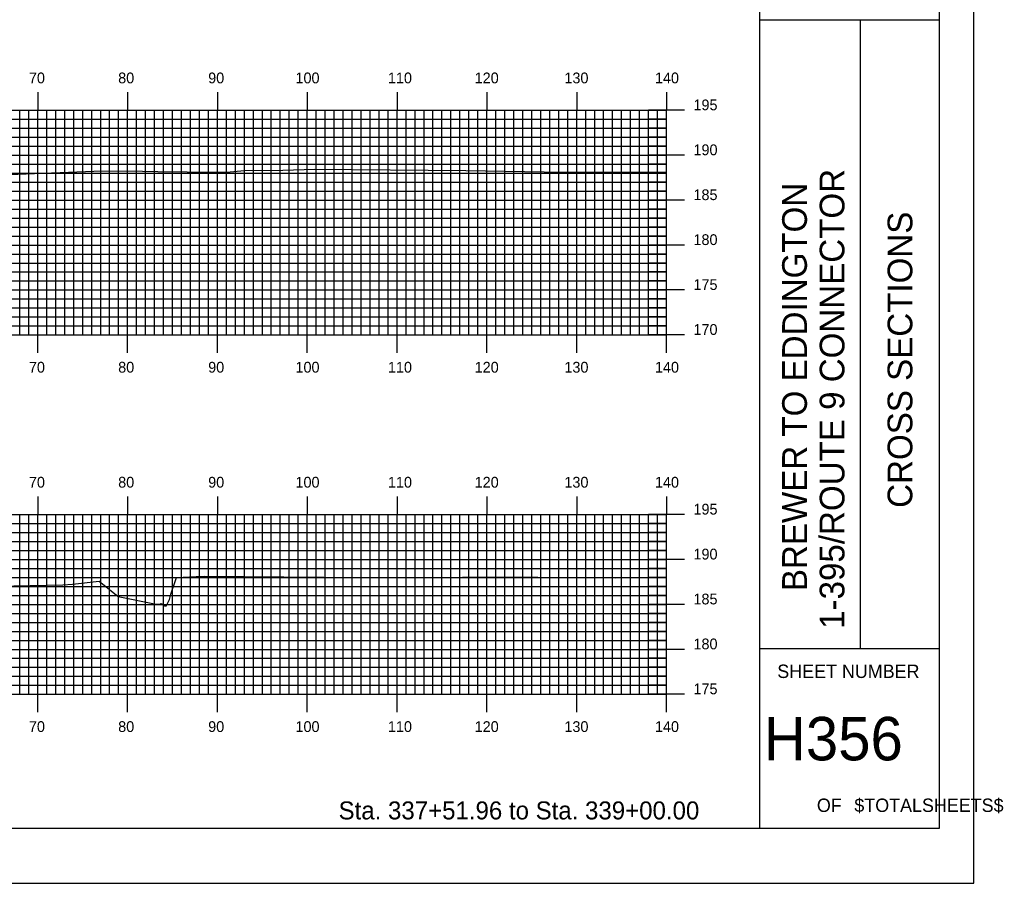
# Model space of a CAD drawing. Extents: x 1823966 to 1824309, y 442591 to 442811.
# Drawn here: x 1824199.8 to 1824309.3, y 442590.5 to 442686.7 of the extents above; entities that cross this region are included whole.
import ezdxf

# ---------------------------------------------------------------- set-up
doc = ezdxf.new("R2010")
doc.units = 0
for name, color, linetype in [('BORDER', 7, 'Continuous'), ('H_V ANNOTATION', 7, 'Continuous'), ('MAJOR', 7, 'Continuous'), ('MINOR', 7, 'Continuous'), ('PLOT BOUNDARY', 7, 'Continuous'), ('S_Roadway_Centerline', 7, 'Continuous')]:
    doc.layers.add(name, color=color, linetype=linetype)

msp = doc.modelspace()

# ---------------------------------------------------------------- linework, layer by layer
at = {"layer": 'BORDER'}
for p, q in [((1824282.22, 442596.67), (1824282.22, 442806.67)), ((1824282.22, 442686.67), (1824302.22, 442686.67)), ((1824293.4, 442616.67), (1824293.4, 442686.67)), ((1824282.22, 442616.67), (1824302.22, 442616.67))]:
    msp.add_line(p, q, dxfattribs=at)
msp.add_lwpolyline([(1823982.22, 442596.67), (1824302.22, 442596.67), (1824302.22, 442806.67), (1823982.22, 442806.67)], close=True, dxfattribs=at)
at = {"layer": 'MAJOR'}
for p, q in [((1824201.82, 442678.59), (1824201.82, 442676.59)), ((1824211.82, 442678.59), (1824211.82, 442676.59)), ((1824221.82, 442678.59), (1824221.82, 442676.59)), ((1824231.82, 442678.59), (1824231.82, 442676.59)), ((1824241.82, 442678.59), (1824241.82, 442676.59)), ((1824251.82, 442678.59), (1824251.82, 442676.59)), ((1824261.82, 442678.59), (1824261.82, 442676.59)), ((1824271.82, 442678.59), (1824271.82, 442676.59)), ((1823991.82, 442676.59), (1824271.82, 442676.59)), ((1823991.82, 442676.59), (1824271.82, 442676.59)), ((1824201.82, 442651.59), (1824201.82, 442676.59)), ((1824211.82, 442651.59), (1824211.82, 442676.59)), ((1824221.82, 442651.59), (1824221.82, 442676.59)), ((1824231.82, 442651.59), (1824231.82, 442676.59)), ((1824241.82, 442651.59), (1824241.82, 442676.59)), ((1824251.82, 442651.59), (1824251.82, 442676.59)), ((1824261.82, 442651.59), (1824261.82, 442676.59)), ((1824273.83, 442676.59), (1824269.82, 442676.59)), ((1824271.82, 442651.59), (1824271.82, 442676.59)), ((1824271.82, 442651.59), (1824271.82, 442676.59)), ((1823991.82, 442671.59), (1824271.82, 442671.59)), ((1824273.83, 442671.59), (1824269.82, 442671.59)), ((1823991.82, 442666.59), (1824271.82, 442666.59)), ((1824273.83, 442666.59), (1824269.82, 442666.59)), ((1823991.82, 442661.59), (1824271.82, 442661.59)), ((1824273.83, 442661.59), (1824269.82, 442661.59)), ((1823991.82, 442656.59), (1824271.82, 442656.59)), ((1824273.83, 442656.59), (1824269.82, 442656.59)), ((1823991.82, 442651.59), (1824271.82, 442651.59)), ((1823991.82, 442651.59), (1824271.82, 442651.59)), ((1824201.82, 442649.58), (1824201.82, 442651.59)), ((1824211.82, 442649.58), (1824211.82, 442651.59)), ((1824221.82, 442649.58), (1824221.82, 442651.59)), ((1824231.82, 442649.58), (1824231.82, 442651.59)), ((1824241.82, 442649.58), (1824241.82, 442651.59)), ((1824251.82, 442649.58), (1824251.82, 442651.59)), ((1824261.82, 442649.58), (1824261.82, 442651.59)), ((1824273.83, 442651.59), (1824269.82, 442651.59)), ((1824271.82, 442649.58), (1824271.82, 442651.59)), ((1824201.82, 442633.59), (1824201.82, 442631.59)), ((1824211.82, 442633.59), (1824211.82, 442631.59)), ((1824221.82, 442633.59), (1824221.82, 442631.59)), ((1824231.82, 442633.59), (1824231.82, 442631.59)), ((1824241.82, 442633.59), (1824241.82, 442631.59)), ((1824251.82, 442633.59), (1824251.82, 442631.59)), ((1824261.82, 442633.59), (1824261.82, 442631.59)), ((1824271.82, 442633.59), (1824271.82, 442631.59)), ((1824131.82, 442631.59), (1824271.82, 442631.59)), ((1824131.82, 442631.59), (1824271.82, 442631.59)), ((1824201.82, 442611.59), (1824201.82, 442631.59)), ((1824211.82, 442611.59), (1824211.82, 442631.59)), ((1824221.82, 442611.59), (1824221.82, 442631.59)), ((1824231.82, 442611.59), (1824231.82, 442631.59)), ((1824241.82, 442611.59), (1824241.82, 442631.59)), ((1824251.82, 442611.59), (1824251.82, 442631.59)), ((1824261.82, 442611.59), (1824261.82, 442631.59)), ((1824273.83, 442631.59), (1824269.82, 442631.59)), ((1824271.82, 442611.59), (1824271.82, 442631.59)), ((1824271.82, 442611.59), (1824271.82, 442631.59)), ((1824131.82, 442626.59), (1824271.82, 442626.59)), ((1824273.83, 442626.59), (1824269.82, 442626.59)), ((1824131.82, 442621.59), (1824271.82, 442621.59)), ((1824273.83, 442621.59), (1824269.82, 442621.59)), ((1824131.82, 442616.59), (1824271.82, 442616.59)), ((1824273.83, 442616.59), (1824269.82, 442616.59)), ((1824131.82, 442611.59), (1824271.82, 442611.59)), ((1824131.82, 442611.59), (1824271.82, 442611.59)), ((1824201.82, 442609.58), (1824201.82, 442611.59)), ((1824211.82, 442609.58), (1824211.82, 442611.59)), ((1824221.82, 442609.58), (1824221.82, 442611.59)), ((1824231.82, 442609.58), (1824231.82, 442611.59)), ((1824241.82, 442609.58), (1824241.82, 442611.59)), ((1824251.82, 442609.58), (1824251.82, 442611.59)), ((1824261.82, 442609.58), (1824261.82, 442611.59)), ((1824273.83, 442611.59), (1824269.82, 442611.59)), ((1824271.82, 442609.58), (1824271.82, 442611.59))]:
    msp.add_line(p, q, dxfattribs=at)
at = {"layer": 'MINOR'}
for p, q in [((1824199.82, 442651.59), (1824199.82, 442676.59)), ((1824200.82, 442651.59), (1824200.82, 442676.59)), ((1824202.82, 442651.59), (1824202.82, 442676.59)), ((1824203.82, 442651.59), (1824203.82, 442676.59)), ((1824204.82, 442651.59), (1824204.82, 442676.59)), ((1824205.82, 442651.59), (1824205.82, 442676.59)), ((1824206.82, 442651.59), (1824206.82, 442676.59)), ((1824207.82, 442651.59), (1824207.82, 442676.59)), ((1824208.82, 442651.59), (1824208.82, 442676.59)), ((1824209.82, 442651.59), (1824209.82, 442676.59)), ((1824210.82, 442651.59), (1824210.82, 442676.59)), ((1824212.82, 442651.59), (1824212.82, 442676.59)), ((1824213.82, 442651.59), (1824213.82, 442676.59)), ((1824214.82, 442651.59), (1824214.82, 442676.59)), ((1824215.82, 442651.59), (1824215.82, 442676.59)), ((1824216.82, 442651.59), (1824216.82, 442676.59)), ((1824217.82, 442651.59), (1824217.82, 442676.59)), ((1824218.82, 442651.59), (1824218.82, 442676.59)), ((1824219.82, 442651.59), (1824219.82, 442676.59)), ((1824220.82, 442651.59), (1824220.82, 442676.59)), ((1824222.82, 442651.59), (1824222.82, 442676.59)), ((1824223.82, 442651.59), (1824223.82, 442676.59)), ((1824224.82, 442651.59), (1824224.82, 442676.59)), ((1824225.82, 442651.59), (1824225.82, 442676.59)), ((1824226.82, 442651.59), (1824226.82, 442676.59)), ((1824227.82, 442651.59), (1824227.82, 442676.59)), ((1824228.82, 442651.59), (1824228.82, 442676.59)), ((1824229.82, 442651.59), (1824229.82, 442676.59)), ((1824230.82, 442651.59), (1824230.82, 442676.59)), ((1824232.82, 442651.59), (1824232.82, 442676.59)), ((1824233.82, 442651.59), (1824233.82, 442676.59)), ((1824234.82, 442651.59), (1824234.82, 442676.59)), ((1824235.82, 442651.59), (1824235.82, 442676.59)), ((1824236.82, 442651.59), (1824236.82, 442676.59)), ((1824237.82, 442651.59), (1824237.82, 442676.59)), ((1824238.82, 442651.59), (1824238.82, 442676.59)), ((1824239.82, 442651.59), (1824239.82, 442676.59)), ((1824240.82, 442651.59), (1824240.82, 442676.59)), ((1824242.82, 442651.59), (1824242.82, 442676.59)), ((1824243.82, 442651.59), (1824243.82, 442676.59)), ((1824244.82, 442651.59), (1824244.82, 442676.59)), ((1824245.82, 442651.59), (1824245.82, 442676.59)), ((1824246.82, 442651.59), (1824246.82, 442676.59)), ((1824247.82, 442651.59), (1824247.82, 442676.59)), ((1824248.82, 442651.59), (1824248.82, 442676.59)), ((1824249.82, 442651.59), (1824249.82, 442676.59)), ((1824250.82, 442651.59), (1824250.82, 442676.59)), ((1824252.82, 442651.59), (1824252.82, 442676.59)), ((1824253.82, 442651.59), (1824253.82, 442676.59)), ((1824254.82, 442651.59), (1824254.82, 442676.59)), ((1824255.82, 442651.59), (1824255.82, 442676.59)), ((1824256.82, 442651.59), (1824256.82, 442676.59)), ((1824257.82, 442651.59), (1824257.82, 442676.59)), ((1824258.82, 442651.59), (1824258.82, 442676.59)), ((1824259.82, 442651.59), (1824259.82, 442676.59)), ((1824260.82, 442651.59), (1824260.82, 442676.59)), ((1824262.82, 442651.59), (1824262.82, 442676.59)), ((1824263.82, 442651.59), (1824263.82, 442676.59)), ((1824264.82, 442651.59), (1824264.82, 442676.59)), ((1824265.82, 442651.59), (1824265.82, 442676.59)), ((1824266.82, 442651.59), (1824266.82, 442676.59)), ((1824267.82, 442651.59), (1824267.82, 442676.59)), ((1824268.82, 442651.59), (1824268.82, 442676.59)), ((1824269.82, 442651.59), (1824269.82, 442676.59)), ((1824270.82, 442651.59), (1824270.82, 442676.59)), ((1823991.82, 442675.59), (1824271.82, 442675.59)), ((1824271.82, 442675.59), (1824269.82, 442675.59)), ((1823991.82, 442674.59), (1824271.82, 442674.59)), ((1824271.82, 442674.59), (1824269.82, 442674.59)), ((1823991.82, 442673.59), (1824271.82, 442673.59)), ((1824271.82, 442673.59), (1824269.82, 442673.59)), ((1823991.82, 442672.59), (1824271.82, 442672.59)), ((1824271.82, 442672.59), (1824269.82, 442672.59)), ((1823991.82, 442670.59), (1824271.82, 442670.59)), ((1824271.82, 442670.59), (1824269.82, 442670.59)), ((1823991.82, 442669.59), (1824271.82, 442669.59)), ((1824271.82, 442669.59), (1824269.82, 442669.59)), ((1823991.82, 442668.59), (1824271.82, 442668.59)), ((1824271.82, 442668.59), (1824269.82, 442668.59)), ((1823991.82, 442667.59), (1824271.82, 442667.59)), ((1824271.82, 442667.59), (1824269.82, 442667.59)), ((1823991.82, 442665.59), (1824271.82, 442665.59)), ((1824271.82, 442665.59), (1824269.82, 442665.59)), ((1823991.82, 442664.59), (1824271.82, 442664.59)), ((1824271.82, 442664.59), (1824269.82, 442664.59)), ((1823991.82, 442663.59), (1824271.82, 442663.59)), ((1824271.82, 442663.59), (1824269.82, 442663.59)), ((1823991.82, 442662.59), (1824271.82, 442662.59)), ((1824271.82, 442662.59), (1824269.82, 442662.59)), ((1823991.82, 442660.59), (1824271.82, 442660.59)), ((1824271.82, 442660.59), (1824269.82, 442660.59)), ((1823991.82, 442659.59), (1824271.82, 442659.59)), ((1824271.82, 442659.59), (1824269.82, 442659.59)), ((1823991.82, 442658.59), (1824271.82, 442658.59)), ((1824271.82, 442658.59), (1824269.82, 442658.59)), ((1823991.82, 442657.59), (1824271.82, 442657.59)), ((1824271.82, 442657.59), (1824269.82, 442657.59)), ((1823991.82, 442655.59), (1824271.82, 442655.59)), ((1823991.82, 442654.59), (1824271.82, 442654.59)), ((1824271.82, 442655.59), (1824269.82, 442655.59)), ((1824271.82, 442654.59), (1824269.82, 442654.59)), ((1823991.82, 442653.59), (1824271.82, 442653.59)), ((1824271.82, 442653.59), (1824269.82, 442653.59)), ((1823991.82, 442652.59), (1824271.82, 442652.59)), ((1824271.82, 442652.59), (1824269.82, 442652.59)), ((1824199.82, 442611.59), (1824199.82, 442631.59)), ((1824200.82, 442611.59), (1824200.82, 442631.59)), ((1824202.82, 442611.59), (1824202.82, 442631.59)), ((1824203.82, 442611.59), (1824203.82, 442631.59)), ((1824204.82, 442611.59), (1824204.82, 442631.59)), ((1824205.82, 442611.59), (1824205.82, 442631.59)), ((1824206.82, 442611.59), (1824206.82, 442631.59)), ((1824207.82, 442611.59), (1824207.82, 442631.59)), ((1824208.82, 442611.59), (1824208.82, 442631.59)), ((1824209.82, 442611.59), (1824209.82, 442631.59)), ((1824210.82, 442611.59), (1824210.82, 442631.59)), ((1824212.82, 442611.59), (1824212.82, 442631.59)), ((1824213.82, 442611.59), (1824213.82, 442631.59)), ((1824214.82, 442611.59), (1824214.82, 442631.59)), ((1824215.82, 442611.59), (1824215.82, 442631.59)), ((1824216.82, 442611.59), (1824216.82, 442631.59)), ((1824217.82, 442611.59), (1824217.82, 442631.59)), ((1824218.82, 442611.59), (1824218.82, 442631.59)), ((1824219.82, 442611.59), (1824219.82, 442631.59)), ((1824220.82, 442611.59), (1824220.82, 442631.59)), ((1824222.82, 442611.59), (1824222.82, 442631.59)), ((1824223.82, 442611.59), (1824223.82, 442631.59)), ((1824224.82, 442611.59), (1824224.82, 442631.59)), ((1824225.82, 442611.59), (1824225.82, 442631.59)), ((1824226.82, 442611.59), (1824226.82, 442631.59)), ((1824227.82, 442611.59), (1824227.82, 442631.59)), ((1824228.82, 442611.59), (1824228.82, 442631.59)), ((1824229.82, 442611.59), (1824229.82, 442631.59)), ((1824230.82, 442611.59), (1824230.82, 442631.59)), ((1824232.82, 442611.59), (1824232.82, 442631.59)), ((1824233.82, 442611.59), (1824233.82, 442631.59)), ((1824234.82, 442611.59), (1824234.82, 442631.59)), ((1824235.82, 442611.59), (1824235.82, 442631.59)), ((1824236.82, 442611.59), (1824236.82, 442631.59)), ((1824237.82, 442611.59), (1824237.82, 442631.59)), ((1824238.82, 442611.59), (1824238.82, 442631.59)), ((1824239.82, 442611.59), (1824239.82, 442631.59)), ((1824240.82, 442611.59), (1824240.82, 442631.59)), ((1824242.82, 442611.59), (1824242.82, 442631.59)), ((1824243.82, 442611.59), (1824243.82, 442631.59)), ((1824244.82, 442611.59), (1824244.82, 442631.59)), ((1824245.82, 442611.59), (1824245.82, 442631.59)), ((1824246.82, 442611.59), (1824246.82, 442631.59)), ((1824247.82, 442611.59), (1824247.82, 442631.59)), ((1824248.82, 442611.59), (1824248.82, 442631.59)), ((1824249.82, 442611.59), (1824249.82, 442631.59)), ((1824250.82, 442611.59), (1824250.82, 442631.59)), ((1824252.82, 442611.59), (1824252.82, 442631.59)), ((1824253.82, 442611.59), (1824253.82, 442631.59)), ((1824254.82, 442611.59), (1824254.82, 442631.59)), ((1824255.82, 442611.59), (1824255.82, 442631.59)), ((1824256.82, 442611.59), (1824256.82, 442631.59)), ((1824257.82, 442611.59), (1824257.82, 442631.59)), ((1824258.82, 442611.59), (1824258.82, 442631.59)), ((1824259.82, 442611.59), (1824259.82, 442631.59)), ((1824260.82, 442611.59), (1824260.82, 442631.59)), ((1824262.82, 442611.59), (1824262.82, 442631.59)), ((1824263.82, 442611.59), (1824263.82, 442631.59)), ((1824264.82, 442611.59), (1824264.82, 442631.59)), ((1824265.82, 442611.59), (1824265.82, 442631.59)), ((1824266.82, 442611.59), (1824266.82, 442631.59)), ((1824267.82, 442611.59), (1824267.82, 442631.59)), ((1824268.82, 442611.59), (1824268.82, 442631.59)), ((1824269.82, 442611.59), (1824269.82, 442631.59)), ((1824270.82, 442611.59), (1824270.82, 442631.59)), ((1824131.82, 442630.59), (1824271.82, 442630.59)), ((1824271.82, 442630.59), (1824269.82, 442630.59)), ((1824131.82, 442629.59), (1824271.82, 442629.59)), ((1824271.82, 442629.59), (1824269.82, 442629.59)), ((1824131.82, 442628.59), (1824271.82, 442628.59)), ((1824271.82, 442628.59), (1824269.82, 442628.59)), ((1824131.82, 442627.59), (1824271.82, 442627.59)), ((1824271.82, 442627.59), (1824269.82, 442627.59)), ((1824131.82, 442625.59), (1824271.82, 442625.59)), ((1824271.82, 442625.59), (1824269.82, 442625.59)), ((1824131.82, 442624.59), (1824271.82, 442624.59)), ((1824271.82, 442624.59), (1824269.82, 442624.59)), ((1824131.82, 442623.59), (1824271.82, 442623.59)), ((1824271.82, 442623.59), (1824269.82, 442623.59)), ((1824131.82, 442622.59), (1824271.82, 442622.59)), ((1824271.82, 442622.59), (1824269.82, 442622.59)), ((1824131.82, 442620.59), (1824271.82, 442620.59)), ((1824131.82, 442619.59), (1824271.82, 442619.59)), ((1824271.82, 442620.59), (1824269.82, 442620.59)), ((1824271.82, 442619.59), (1824269.82, 442619.59)), ((1824131.82, 442618.59), (1824271.82, 442618.59)), ((1824271.82, 442618.59), (1824269.82, 442618.59)), ((1824131.82, 442617.59), (1824271.82, 442617.59)), ((1824271.82, 442617.59), (1824269.82, 442617.59)), ((1824131.82, 442615.59), (1824271.82, 442615.59)), ((1824271.82, 442615.59), (1824269.82, 442615.59)), ((1824131.82, 442614.59), (1824271.82, 442614.59)), ((1824271.82, 442614.59), (1824269.82, 442614.59)), ((1824131.82, 442613.59), (1824271.82, 442613.59)), ((1824271.82, 442613.59), (1824269.82, 442613.59)), ((1824131.82, 442612.59), (1824271.82, 442612.59)), ((1824271.82, 442612.59), (1824269.82, 442612.59))]:
    msp.add_line(p, q, dxfattribs=at)
at = {"layer": 'PLOT BOUNDARY'}
msp.add_lwpolyline([(1823966.04, 442590.55), (1824306.04, 442590.55), (1824306.04, 442810.55), (1823966.04, 442810.55)], close=True, dxfattribs=at)
at = {"layer": 'S_Roadway_Centerline'}
for points in [[(1824187.33, 442669), (1824208.05, 442669.83), (1824210.83, 442669.85), (1824213.46, 442669.8), (1824215.2, 442669.79), (1824221.7, 442669.69), (1824222.86, 442669.72), (1824224.78, 442669.9), (1824229.1, 442669.93), (1824232.67, 442670.03), (1824249.49, 442669.9), (1824258.2, 442669.73), (1824263.5, 442669.69), (1824271.82, 442669.69)], [(1824197.31, 442623.63), (1824204.61, 442623.78), (1824205.67, 442623.84), (1824208.65, 442624.17), (1824210.75, 442622.48), (1824214.81, 442621.67), (1824215.42, 442621.62), (1824215.57, 442621.7), (1824215.86, 442621.49), (1824216.05, 442621.41), (1824216.06, 442621.54), (1824216.1, 442621.41), (1824216.48, 442622.12), (1824216.62, 442622.73), (1824217.25, 442624.57), (1824219.45, 442624.68), (1824220.35, 442624.73), (1824238.12, 442624.57), (1824240.03, 442624.59), (1824249.09, 442624.61), (1824257.5, 442624.63), (1824266.16, 442624.54), (1824271.82, 442624.58)]]:
    msp.add_lwpolyline(points, dxfattribs=at)

# ---------------------------------------------------------------- texts
at = {"layer": 'BORDER'}
for s, p in [('1-395/ROUTE 9 CONNECTOR', (1824291.63, 442618.87)), ('BREWER TO EDDINGTON', (1824287.45, 442623.07)), ('CROSS SECTIONS', (1824299.19, 442632.34))]:
    msp.add_text(s, height=2.7557, rotation=90, dxfattribs=at).set_placement(p)
for s, height, p in [('SHEET NUMBER', 1.4905, (1824284.15, 442613.4)), ('H356', 4.839, (1824282.66, 442604.23)), ('OF', 1.491, (1824288.56, 442598.49)), ('$TOTALSHEETS$', 1.4905, (1824292.73, 442598.49))]:
    msp.add_text(s, height=height, dxfattribs=at).set_placement(p)
at = {"layer": 'H_V ANNOTATION'}
for s, height, p in [('70', 1.2, (1824200.83, 442679.59)), ('80', 1.2, (1824210.77, 442679.59)), ('90', 1.2, (1824220.79, 442679.59)), ('100', 1.2, (1824230.51, 442679.59)), ('110', 1.2, (1824240.8, 442679.59)), ('120', 1.2, (1824250.46, 442679.59)), ('130', 1.2, (1824260.45, 442679.59)), ('140', 1.2, (1824270.53, 442679.59)), ('195', 1.2, (1824274.82, 442676.59)), ('190', 1.2, (1824274.82, 442671.59)), ('185', 1.2, (1824274.82, 442666.59)), ('180', 1.2, (1824274.82, 442661.59)), ('175', 1.2, (1824274.82, 442656.59)), ('170', 1.2, (1824274.82, 442651.59)), ('70', 1.2, (1824200.83, 442647.39)), ('80', 1.2, (1824210.77, 442647.39)), ('90', 1.2, (1824220.79, 442647.39)), ('100', 1.2, (1824230.51, 442647.39)), ('110', 1.2, (1824240.8, 442647.39)), ('120', 1.2, (1824250.46, 442647.39)), ('130', 1.2, (1824260.45, 442647.39)), ('140', 1.2, (1824270.53, 442647.39)), ('70', 1.2, (1824200.83, 442634.59)), ('80', 1.2, (1824210.77, 442634.59)), ('90', 1.2, (1824220.79, 442634.59)), ('100', 1.2, (1824230.51, 442634.59)), ('110', 1.2, (1824240.8, 442634.59)), ('120', 1.2, (1824250.46, 442634.59)), ('130', 1.2, (1824260.45, 442634.59)), ('140', 1.2, (1824270.53, 442634.59)), ('195', 1.2, (1824274.82, 442631.59)), ('190', 1.2, (1824274.82, 442626.59)), ('185', 1.2, (1824274.82, 442621.59)), ('180', 1.2, (1824274.82, 442616.59)), ('175', 1.2, (1824274.82, 442611.59)), ('70', 1.2, (1824200.83, 442607.39)), ('80', 1.2, (1824210.77, 442607.39)), ('90', 1.2, (1824220.79, 442607.39)), ('100', 1.2, (1824230.51, 442607.39)), ('110', 1.2, (1824240.8, 442607.39)), ('120', 1.2, (1824250.46, 442607.39)), ('130', 1.2, (1824260.45, 442607.39)), ('140', 1.2, (1824270.53, 442607.39)), ('Sta. 337+51.96 to Sta. 339+00.00', 2.0004, (1824235.31, 442597.66))]:
    msp.add_text(s, height=height, dxfattribs=at).set_placement(p)

doc.saveas('drawing.dxf')
